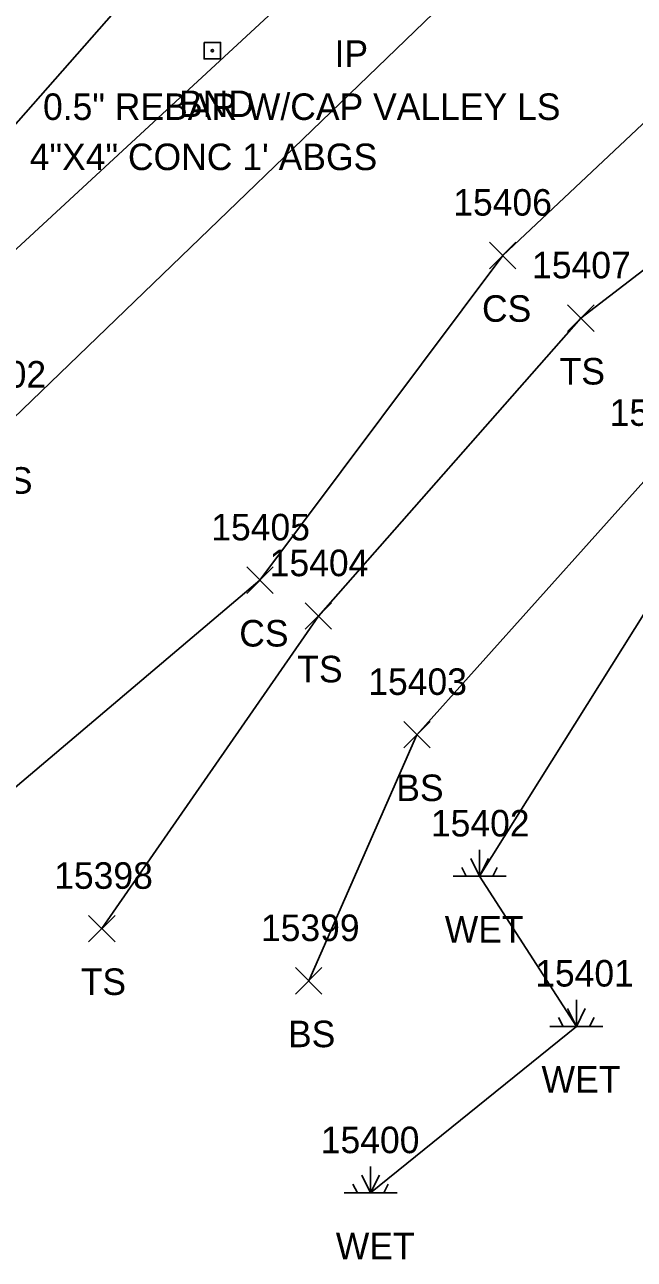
# Model space of a CAD drawing. Extents: x 1606530 to 1613020, y 784959 to 789666.
# Drawn here: x 1609059.8 to 1609105.8, y 788242.4 to 788335.5 of the extents above; entities that cross this region are included whole.
import ezdxf

# ---------------------------------------------------------------- set-up
doc = ezdxf.new("R2010")
doc.units = 0
for name, color, linetype in [('L_A', 7, 'Continuous'), ('L_I', 7, 'Continuous'), ('L_TIC', 7, 'Continuous'), ('LAWA', 7, 'Continuous'), ('LELB', 7, 'Continuous'), ('LWET', 7, 'Continuous'), ('M_A', 7, 'Continuous'), ('M_C', 7, 'Continuous'), ('MHBP', 7, 'Continuous')]:
    doc.layers.add(name, color=color, linetype=linetype)

msp = doc.modelspace()

# ---------------------------------------------------------------- linework, layer by layer
at = {"layer": 'L_TIC'}
for points in [[(1609094.849, 788317.069), (1609096.849, 788319.069)], [(1609096.849, 788317.069), (1609094.849, 788319.069)], [(1609100.735, 788312.342), (1609102.735, 788314.342)], [(1609102.735, 788312.342), (1609100.735, 788314.342)], [(1609076.554, 788292.594), (1609078.554, 788294.594)], [(1609078.554, 788292.594), (1609076.554, 788294.594)], [(1609080.959, 788289.895), (1609082.959, 788291.895)], [(1609082.959, 788289.895), (1609080.959, 788291.895)], [(1609088.388, 788280.947), (1609090.388, 788282.947)], [(1609090.388, 788280.947), (1609088.388, 788282.947)], [(1609064.635, 788266.334), (1609066.635, 788268.334)], [(1609066.635, 788266.334), (1609064.635, 788268.334)], [(1609080.227, 788262.396), (1609082.227, 788264.396)], [(1609082.227, 788262.396), (1609080.227, 788264.396)]]:
    msp.add_lwpolyline(points, dxfattribs=at)
at = {"layer": 'LAWA'}
msp.add_lwpolyline([(1609030.558, 788292.644), (1609056.025, 788324.438), (1609082.563, 788354.607), (1609090.163, 788369.421), (1609097.263, 788381.318), (1609109.225, 788386.029), (1609115.481, 788389.157), (1609124.652, 788392.268), (1609168.817, 788397.242), (1609199.024, 788403.22), (1609247.618, 788406.183), (1609289.075, 788410.022), (1609331.313, 788409.888), (1609380.075, 788411.965), (1609422.468, 788410.639), (1609441.897, 788412.637), (1609456.944, 788393.193), (1609459.972, 788389.839), (1609451.94, 788379.298), (1609445.608, 788371.597)], dxfattribs=at)
at = {"layer": 'LELB'}
for points in [[(1609065.635, 788267.334), (1609081.959, 788290.895), (1609101.735, 788313.342), (1609121.944, 788328.842), (1609120.749, 788351.638), (1609128.026, 788374.505), (1609144.734, 788378.396), (1609178.081, 788389.176), (1609191.957, 788391.406), (1609197.675, 788378.651), (1609184.805, 788360.047), (1609179.632, 788359.129)], [(1609053.661, 788273.38), (1609077.554, 788293.594), (1609095.849, 788318.069), (1609115.192, 788336.223), (1609111.131, 788353.774), (1609121.968, 788374.067), (1609132.129, 788390.339), (1609178.081, 788389.176)], [(1609044.685, 788283.597), (1609058.258, 788305.111), (1609096.979, 788342.471), (1609105.849, 788363.204), (1609115.481, 788389.157)], [(1609038.437, 788287.942), (1609056.526, 788316.096), (1609093.182, 788350), (1609102.909, 788366.579), (1609109.225, 788386.029)], [(1609081.227, 788263.396), (1609089.388, 788281.947), (1609107.582, 788302.227), (1609121.692, 788312.329), (1609125.649, 788321.256), (1609126.42, 788350.584), (1609137.603, 788366.797), (1609155.353, 788377.552), (1609174.448, 788383.669)]]:
    msp.add_lwpolyline(points, dxfattribs=at)
at = {"layer": 'LWET'}
for p, q in [((1609094.108, 788271.279), (1609094.108, 788273.279)), ((1609093.108, 788271.279), (1609092.775, 788271.945)), ((1609094.108, 788271.279), (1609093.442, 788272.612)), ((1609094.108, 788271.279), (1609094.775, 788272.612)), ((1609095.108, 788271.279), (1609095.442, 788271.945)), ((1609096.108, 788271.279), (1609092.108, 788271.279)), ((1609101.402, 788259.968), (1609101.402, 788261.968)), ((1609100.402, 788259.968), (1609100.069, 788260.634)), ((1609101.402, 788259.968), (1609100.735, 788261.301)), ((1609101.402, 788259.968), (1609102.069, 788261.301)), ((1609102.402, 788259.968), (1609102.735, 788260.634)), ((1609103.402, 788259.968), (1609099.402, 788259.968)), ((1609085.895, 788247.41), (1609085.228, 788248.744)), ((1609085.895, 788247.41), (1609085.895, 788249.41)), ((1609085.895, 788247.41), (1609086.561, 788248.744)), ((1609084.895, 788247.41), (1609084.561, 788248.077)), ((1609086.895, 788247.41), (1609087.228, 788248.077)), ((1609087.895, 788247.41), (1609083.895, 788247.41))]:
    msp.add_line(p, q, dxfattribs=at)
msp.add_lwpolyline([(1609085.895, 788247.41), (1609101.402, 788259.968), (1609094.108, 788271.279), (1609111.261, 788298.658), (1609124.037, 788304.764), (1609123.79, 788296.233)], dxfattribs=at)
at = {"layer": 'MHBP'}
msp.add_lwpolyline([(1609073.341, 788334.126), (1609074.591, 788334.126), (1609074.591, 788332.876), (1609073.341, 788332.876)], close=True, dxfattribs=at)
msp.add_circle((1609073.966, 788333.501), 0.0833, dxfattribs=at)

# ---------------------------------------------------------------- texts
at = {"layer": 'L_A'}
for s, p in [('CS', (1609094.29, 788313.069)), ('TS', (1609100.145, 788308.342)), ('CS', (1609056.699, 788300.111)), ('CS', (1609075.995, 788288.594)), ('TS', (1609080.369, 788285.895)), ('BS', (1609087.829, 788276.947)), ('WET', (1609091.486, 788266.279)), ('TS', (1609064.044, 788262.334)), ('BS', (1609079.668, 788258.396)), ('WET', (1609098.78, 788254.968)), ('WET', (1609083.273, 788242.41))]:
    msp.add_text(s, height=2, dxfattribs=at).set_placement(p)
at = {"layer": 'L_I'}
for s, p in [('15406', (1609092.124, 788321.069)), ('15407', (1609098.066, 788316.342)), ('1402', (1609055.487, 788308.111)), ('15408', (1609103.913, 788305.227)), ('15405', (1609073.885, 788296.594)), ('15404', (1609078.29, 788293.895)), ('15403', (1609085.719, 788284.947)), ('15402', (1609090.439, 788274.279)), ('15398', (1609062.044, 788270.334)), ('15399', (1609077.629, 788266.396)), ('15401', (1609098.3, 788262.968)), ('15400', (1609082.139, 788250.41))]:
    msp.add_text(s, height=2, dxfattribs=at).set_placement(p)
at = {"layer": 'M_A'}
for s, p in [('IP', (1609083.179, 788332.281)), ('BND', (1609071.454, 788328.501))]:
    msp.add_text(s, height=2, dxfattribs=at).set_placement(p)
at = {"layer": 'M_C'}
for s, p in [('0.5" REBAR W/CAP VALLEY LS', (1609061.203, 788328.281)), ('4"X4" CONC 1\' ABGS', (1609060.203, 788324.501))]:
    msp.add_text(s, height=2, dxfattribs=at).set_placement(p)

doc.saveas('drawing.dxf')
